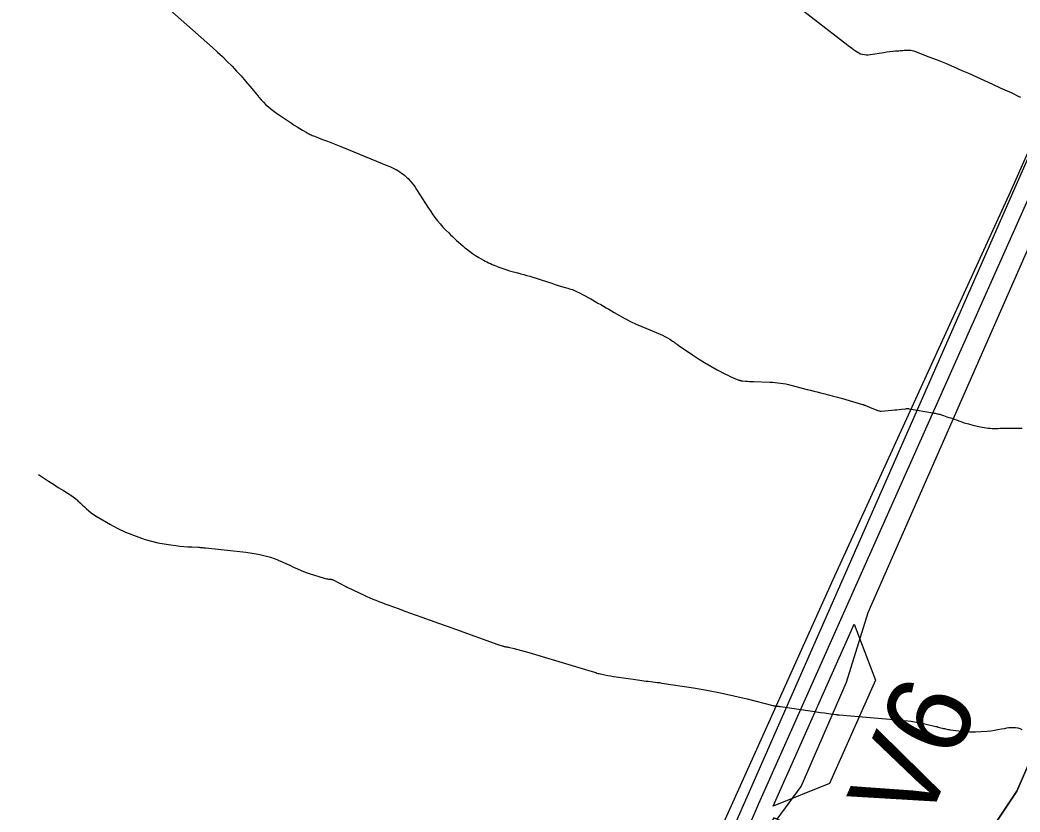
# Model space of a CAD drawing. Extents: x -629976 to -626966, y -1086511 to -1082952.
# Drawn here: x -628720.4 to -628543.5, y -1085440.3 to -1085300.1 of the extents above; entities that cross this region are included whole.
import ezdxf

# ---------------------------------------------------------------- set-up
doc = ezdxf.new("R2010")
doc.units = 0
for name, color, linetype in [('01_PARCELY_NÁVRH_PC', 7, 'Continuous'), ('01_VRSTEVNICE', 7, 'Continuous'), ('02_KULTURY STAV', 7, 'Continuous'), ('03_PC_NÁVRH', 7, 'Continuous'), ('03_PC_OBJEKTY_NÁVRH', 7, 'Continuous')]:
    doc.layers.add(name, color=color, linetype=linetype)

msp = doc.modelspace()

# ---------------------------------------------------------------- linework, layer by layer
at = {"layer": '01_PARCELY_NÁVRH_PC'}
for points in [[(-628504.59, -1085239), (-628671.58, -1085619.06)], [(-628665.65, -1085621.72), (-628622.61, -1085523.77), (-628623.14, -1085523.92), (-628620.48, -1085517.91), (-628606.61, -1085486.09), (-628587.08, -1085441.31), (-628586.49, -1085441.56), (-628582.26, -1085435.74), (-628574.23, -1085417.3), (-628570.41, -1085404.96), (-628501.92, -1085249.09)]]:
    msp.add_lwpolyline(points, dxfattribs=at)
at = {"layer": '01_VRSTEVNICE'}
for points in [[(-628697.46, -1085295.07), (-628686.37, -1085304.93), (-628685.49, -1085305.73), (-628684.62, -1085306.55), (-628683.77, -1085307.38), (-628682.94, -1085308.23), (-628682.12, -1085309.09), (-628681.32, -1085309.97), (-628680.55, -1085310.87), (-628679.78, -1085311.79), (-628678.57, -1085313.27), (-628678.18, -1085313.73), (-628677.78, -1085314.18), (-628677.36, -1085314.62), (-628676.94, -1085315.05), (-628676.49, -1085315.45), (-628676.03, -1085315.84), (-628675.55, -1085316.21), (-628675.06, -1085316.56), (-628672.41, -1085318.33), (-628671.93, -1085318.65), (-628671.44, -1085318.96), (-628670.95, -1085319.26), (-628670.46, -1085319.56), (-628669.82, -1085319.94), (-628669.64, -1085320.04), (-628669.47, -1085320.14), (-628669.29, -1085320.23), (-628669.11, -1085320.32), (-628668.92, -1085320.41), (-628668.74, -1085320.49), (-628668.55, -1085320.57), (-628668.37, -1085320.64), (-628666.96, -1085321.19), (-628666.07, -1085321.54), (-628665.19, -1085321.89), (-628664.3, -1085322.24), (-628663.41, -1085322.6), (-628655.39, -1085325.85), (-628655.02, -1085326), (-628654.66, -1085326.17), (-628654.3, -1085326.34), (-628653.95, -1085326.52), (-628653.92, -1085326.54), (-628653.59, -1085326.73), (-628653.26, -1085326.93), (-628652.95, -1085327.15), (-628652.64, -1085327.37), (-628652.34, -1085327.61), (-628652.06, -1085327.87), (-628651.79, -1085328.14), (-628651.52, -1085328.41), (-628651.41, -1085328.54), (-628651.11, -1085328.9), (-628650.82, -1085329.27), (-628650.55, -1085329.65), (-628650.29, -1085330.04), (-628648.72, -1085332.56), (-628648.32, -1085333.19), (-628647.91, -1085333.8), (-628647.49, -1085334.41), (-628647.05, -1085335.01), (-628646.6, -1085335.6), (-628646.13, -1085336.17), (-628645.63, -1085336.71), (-628645.11, -1085337.24), (-628644.61, -1085337.73), (-628644.26, -1085338.07), (-628643.91, -1085338.41), (-628643.56, -1085338.75), (-628643.21, -1085339.08), (-628642.85, -1085339.41), (-628642.48, -1085339.74), (-628642.12, -1085340.05), (-628641.74, -1085340.37), (-628641.46, -1085340.59), (-628640.94, -1085341), (-628640.4, -1085341.39), (-628639.84, -1085341.75), (-628639.27, -1085342.1), (-628638.46, -1085342.56), (-628638.15, -1085342.73), (-628637.85, -1085342.89), (-628637.54, -1085343.05), (-628637.22, -1085343.19), (-628636.91, -1085343.33), (-628636.59, -1085343.47), (-628636.27, -1085343.6), (-628635.95, -1085343.73), (-628635.9, -1085343.75), (-628635.56, -1085343.88), (-628635.21, -1085344.01), (-628634.86, -1085344.13), (-628634.51, -1085344.25), (-628634.31, -1085344.31), (-628633.85, -1085344.44), (-628633.39, -1085344.58), (-628632.93, -1085344.7), (-628632.47, -1085344.82), (-628632.35, -1085344.85), (-628631.83, -1085344.98), (-628631.31, -1085345.12), (-628630.79, -1085345.28), (-628630.28, -1085345.43), (-628626.94, -1085346.5), (-628626.36, -1085346.68), (-628625.79, -1085346.86), (-628625.22, -1085347.04), (-628624.65, -1085347.22), (-628624.02, -1085347.41), (-628623.76, -1085347.48), (-628623.5, -1085347.56), (-628623.24, -1085347.64), (-628622.98, -1085347.72), (-628622.73, -1085347.8), (-628622.47, -1085347.89), (-628622.23, -1085348), (-628621.98, -1085348.12), (-628621.45, -1085348.38), (-628620.95, -1085348.64), (-628620.45, -1085348.9), (-628619.95, -1085349.18), (-628619.46, -1085349.45), (-628619.16, -1085349.62), (-628618.68, -1085349.9), (-628618.2, -1085350.17), (-628617.72, -1085350.45), (-628617.24, -1085350.72), (-628616.76, -1085351), (-628616.28, -1085351.28), (-628615.81, -1085351.56), (-628615.33, -1085351.84), (-628614.38, -1085352.39), (-628613.42, -1085352.93), (-628612.44, -1085353.44), (-628611.45, -1085353.91), (-628610.44, -1085354.35), (-628607.21, -1085355.68), (-628606.77, -1085355.87), (-628606.34, -1085356.08), (-628605.92, -1085356.32), (-628605.5, -1085356.57), (-628604.99, -1085356.9), (-628604.84, -1085356.99), (-628604.7, -1085357.1), (-628604.56, -1085357.2), (-628604.42, -1085357.31), (-628604.28, -1085357.42), (-628604.14, -1085357.53), (-628604, -1085357.63), (-628603.85, -1085357.73), (-628601.49, -1085359.34), (-628600.42, -1085360.05), (-628599.33, -1085360.72), (-628598.22, -1085361.36), (-628597.09, -1085361.98), (-628595.63, -1085362.74), (-628595.22, -1085362.95), (-628594.81, -1085363.15), (-628594.39, -1085363.34), (-628593.96, -1085363.51), (-628593.26, -1085363.8), (-628593.18, -1085363.83), (-628593.1, -1085363.85), (-628593.02, -1085363.88), (-628592.94, -1085363.9), (-628592.86, -1085363.92), (-628592.77, -1085363.93), (-628592.69, -1085363.94), (-628592.6, -1085363.95), (-628592.08, -1085364), (-628591.74, -1085364.02), (-628591.39, -1085364.04), (-628591.04, -1085364.06), (-628590.7, -1085364.07), (-628587.8, -1085364.17), (-628587.33, -1085364.19), (-628586.85, -1085364.22), (-628586.38, -1085364.27), (-628585.91, -1085364.33), (-628585.44, -1085364.41), (-628584.97, -1085364.5), (-628584.51, -1085364.6), (-628584.05, -1085364.71), (-628581.19, -1085365.45), (-628580.59, -1085365.61), (-628580, -1085365.76), (-628579.41, -1085365.91), (-628578.82, -1085366.06), (-628578.54, -1085366.13), (-628578.09, -1085366.25), (-628577.64, -1085366.36), (-628577.19, -1085366.47), (-628576.74, -1085366.59), (-628576.29, -1085366.7), (-628575.84, -1085366.82), (-628575.39, -1085366.94), (-628574.95, -1085367.07), (-628571.38, -1085368.11), (-628571.33, -1085368.13), (-628571.27, -1085368.15), (-628571.22, -1085368.17), (-628571.17, -1085368.18), (-628571.12, -1085368.2), (-628571.07, -1085368.22), (-628571.02, -1085368.25), (-628570.97, -1085368.27), (-628569.73, -1085368.8), (-628569.58, -1085368.86), (-628569.44, -1085368.92), (-628569.3, -1085368.97), (-628569.15, -1085369.03), (-628569.13, -1085369.04), (-628569, -1085369.08), (-628568.86, -1085369.13), (-628568.73, -1085369.17), (-628568.6, -1085369.21), (-628568.4, -1085369.27), (-628568.36, -1085369.28), (-628568.33, -1085369.29), (-628568.29, -1085369.3), (-628568.25, -1085369.31), (-628568.21, -1085369.31), (-628568.17, -1085369.31), (-628568.13, -1085369.31), (-628568.09, -1085369.31), (-628566.19, -1085369.13), (-628565.76, -1085369.09), (-628565.33, -1085369.05), (-628564.9, -1085369), (-628564.47, -1085368.96), (-628563.74, -1085368.88), (-628563.67, -1085368.87), (-628563.6, -1085368.87), (-628563.54, -1085368.86), (-628563.47, -1085368.86), (-628563.39, -1085368.86), (-628563.36, -1085368.86), (-628563.33, -1085368.86), (-628563.3, -1085368.86), (-628563.27, -1085368.87), (-628563.24, -1085368.87), (-628563.21, -1085368.88), (-628563.18, -1085368.88), (-628563.15, -1085368.89), (-628558.98, -1085369.61), (-628558.77, -1085369.65), (-628558.57, -1085369.69), (-628558.36, -1085369.73), (-628558.15, -1085369.77), (-628557.94, -1085369.82), (-628557.74, -1085369.87), (-628557.54, -1085369.93), (-628557.33, -1085370), (-628557.09, -1085370.08), (-628556.77, -1085370.19), (-628556.45, -1085370.3), (-628556.12, -1085370.41), (-628555.8, -1085370.52), (-628554.16, -1085371.1), (-628553.4, -1085371.35), (-628552.64, -1085371.58), (-628551.87, -1085371.78), (-628551.1, -1085371.96), (-628550.22, -1085372.15), (-628549.88, -1085372.22), (-628549.53, -1085372.27), (-628549.19, -1085372.31), (-628548.84, -1085372.34), (-628548.8, -1085372.35), (-628548.47, -1085372.36), (-628548.13, -1085372.37), (-628547.8, -1085372.37), (-628547.46, -1085372.36), (-628547.13, -1085372.34), (-628546.79, -1085372.33), (-628546.46, -1085372.32), (-628546.12, -1085372.32), (-628544.98, -1085372.3), (-628544.08, -1085372.31), (-628543.17, -1085372.35)], [(-628583.63, -1085297.1), (-628574.74, -1085303.93), (-628574.3, -1085304.27), (-628573.85, -1085304.61), (-628573.41, -1085304.95), (-628572.97, -1085305.28), (-628572.63, -1085305.54), (-628572.34, -1085305.72), (-628572.05, -1085305.89), (-628571.73, -1085306.02), (-628571.41, -1085306.12), (-628571.07, -1085306.19), (-628570.74, -1085306.22), (-628570.4, -1085306.22), (-628570.06, -1085306.18), (-628567.61, -1085305.79), (-628567.09, -1085305.71), (-628566.58, -1085305.64), (-628566.06, -1085305.58), (-628565.54, -1085305.54), (-628565, -1085305.49), (-628564.75, -1085305.47), (-628564.5, -1085305.45), (-628564.25, -1085305.43), (-628564.01, -1085305.41), (-628563.96, -1085305.41), (-628563.73, -1085305.4), (-628563.51, -1085305.39), (-628563.28, -1085305.39), (-628563.05, -1085305.4), (-628562.83, -1085305.42), (-628562.61, -1085305.45), (-628562.39, -1085305.51), (-628562.18, -1085305.58), (-628559.66, -1085306.56), (-628558.19, -1085307.14), (-628556.73, -1085307.73), (-628555.27, -1085308.35), (-628553.82, -1085308.98), (-628552.64, -1085309.5), (-628551.23, -1085310.13), (-628549.83, -1085310.76), (-628548.42, -1085311.39), (-628547.02, -1085312.04), (-628545, -1085312.97), (-628544.62, -1085313.15), (-628544.23, -1085313.34), (-628543.85, -1085313.53), (-628543.47, -1085313.73)], [(-628717.17, -1085380.55), (-628716.3, -1085381.13), (-628715.43, -1085381.7), (-628714.55, -1085382.26), (-628713.67, -1085382.81), (-628712.77, -1085383.35), (-628711.9, -1085383.87), (-628711.45, -1085384.16), (-628711.02, -1085384.46), (-628710.6, -1085384.8), (-628710.2, -1085385.15), (-628710.2, -1085385.16), (-628709.81, -1085385.52), (-628709.43, -1085385.89), (-628709.05, -1085386.26), (-628708.67, -1085386.63), (-628708.28, -1085386.98), (-628707.88, -1085387.32), (-628707.45, -1085387.62), (-628707, -1085387.9), (-628704.46, -1085389.37), (-628703.13, -1085390.08), (-628701.78, -1085390.73), (-628700.39, -1085391.29), (-628698.98, -1085391.8), (-628698.33, -1085392.01), (-628697.21, -1085392.33), (-628696.08, -1085392.61), (-628694.94, -1085392.83), (-628693.78, -1085393), (-628692.88, -1085393.11), (-628692.17, -1085393.19), (-628691.45, -1085393.25), (-628690.74, -1085393.31), (-628690.02, -1085393.35), (-628688.93, -1085393.41), (-628688.76, -1085393.42), (-628688.59, -1085393.43), (-628688.42, -1085393.44), (-628688.25, -1085393.45), (-628688.08, -1085393.47), (-628687.92, -1085393.48), (-628687.75, -1085393.5), (-628687.58, -1085393.52), (-628682.68, -1085394.02), (-628681.58, -1085394.15), (-628680.49, -1085394.29), (-628679.4, -1085394.47), (-628678.31, -1085394.66), (-628677.54, -1085394.81), (-628676.85, -1085394.96), (-628676.16, -1085395.15), (-628675.5, -1085395.38), (-628674.84, -1085395.64), (-628674.77, -1085395.67), (-628674.09, -1085395.97), (-628673.41, -1085396.28), (-628672.73, -1085396.59), (-628672.06, -1085396.92), (-628672.05, -1085396.92), (-628671.37, -1085397.24), (-628670.68, -1085397.53), (-628669.98, -1085397.79), (-628669.27, -1085398.04), (-628666.61, -1085398.89), (-628666.43, -1085398.94), (-628666.24, -1085398.98), (-628666.04, -1085399.01), (-628665.85, -1085399.04), (-628665.6, -1085399.06), (-628665.53, -1085399.06), (-628665.46, -1085399.07), (-628665.39, -1085399.08), (-628665.33, -1085399.09), (-628665.26, -1085399.11), (-628665.19, -1085399.13), (-628665.13, -1085399.15), (-628665.07, -1085399.18), (-628662.8, -1085400.37), (-628662.78, -1085400.38), (-628662.76, -1085400.39), (-628662.74, -1085400.4), (-628662.72, -1085400.41), (-628662.7, -1085400.42), (-628662.68, -1085400.43), (-628662.65, -1085400.44), (-628662.63, -1085400.46), (-628662.61, -1085400.47), (-628662.58, -1085400.48), (-628662.54, -1085400.5), (-628662.51, -1085400.52), (-628662.47, -1085400.53), (-628659.58, -1085401.89), (-628659.06, -1085402.13), (-628658.54, -1085402.36), (-628658.02, -1085402.58), (-628657.49, -1085402.8), (-628656.96, -1085403.01), (-628656.43, -1085403.21), (-628655.9, -1085403.41), (-628655.37, -1085403.61), (-628654.4, -1085403.96), (-628653.39, -1085404.33), (-628652.37, -1085404.7), (-628651.36, -1085405.06), (-628650.34, -1085405.43), (-628649.38, -1085405.77), (-628647.89, -1085406.31), (-628646.4, -1085406.85), (-628644.9, -1085407.38), (-628643.41, -1085407.92), (-628635.92, -1085410.63), (-628635.74, -1085410.69), (-628635.55, -1085410.75), (-628635.35, -1085410.81), (-628635.16, -1085410.87), (-628635.02, -1085410.91), (-628634.9, -1085410.94), (-628634.78, -1085410.97), (-628634.66, -1085410.99), (-628634.53, -1085411.02), (-628634.41, -1085411.04), (-628634.29, -1085411.06), (-628634.17, -1085411.09), (-628634.05, -1085411.12), (-628633, -1085411.36), (-628632.35, -1085411.51), (-628631.71, -1085411.67), (-628631.07, -1085411.85), (-628630.44, -1085412.03), (-628619.22, -1085415.42), (-628619.01, -1085415.49), (-628618.81, -1085415.55), (-628618.6, -1085415.61), (-628618.39, -1085415.67), (-628618.17, -1085415.73), (-628617.96, -1085415.78), (-628617.75, -1085415.83), (-628617.54, -1085415.88), (-628616.97, -1085415.99), (-628616.46, -1085416.09), (-628615.96, -1085416.18), (-628615.46, -1085416.26), (-628614.96, -1085416.34), (-628611.58, -1085416.83), (-628611.2, -1085416.89), (-628610.82, -1085416.94), (-628610.44, -1085416.99), (-628610.06, -1085417.04), (-628609.67, -1085417.09), (-628609.29, -1085417.14), (-628608.91, -1085417.18), (-628608.52, -1085417.23), (-628608.5, -1085417.23), (-628608.1, -1085417.28), (-628607.71, -1085417.33), (-628607.31, -1085417.38), (-628606.92, -1085417.44), (-628601.31, -1085418.31), (-628598.92, -1085418.71), (-628596.53, -1085419.17), (-628594.16, -1085419.69), (-628591.8, -1085420.26), (-628587.29, -1085421.42), (-628587.19, -1085421.44), (-628587.09, -1085421.46), (-628586.99, -1085421.48), (-628586.89, -1085421.5), (-628586.81, -1085421.51), (-628586.75, -1085421.52), (-628586.69, -1085421.53), (-628586.64, -1085421.53), (-628586.58, -1085421.54), (-628586.52, -1085421.54), (-628586.46, -1085421.55), (-628586.41, -1085421.55), (-628586.35, -1085421.56), (-628586.29, -1085421.56), (-628586.2, -1085421.57), (-628586.11, -1085421.58), (-628586.02, -1085421.59), (-628585.93, -1085421.6), (-628580.22, -1085422.44), (-628579.51, -1085422.54), (-628578.81, -1085422.65), (-628578.1, -1085422.74), (-628577.39, -1085422.84), (-628576.12, -1085423.02), (-628576.05, -1085423.03), (-628575.98, -1085423.04), (-628575.9, -1085423.04), (-628575.83, -1085423.05), (-628575.76, -1085423.06), (-628575.69, -1085423.06), (-628575.62, -1085423.07), (-628575.54, -1085423.07), (-628565.23, -1085423.94), (-628564.01, -1085424.06), (-628562.8, -1085424.22), (-628561.59, -1085424.44), (-628560.39, -1085424.68), (-628558.44, -1085425.12), (-628558.21, -1085425.17), (-628557.99, -1085425.23), (-628557.77, -1085425.29), (-628557.55, -1085425.35), (-628557.52, -1085425.36), (-628557.31, -1085425.41), (-628557.11, -1085425.47), (-628556.9, -1085425.52), (-628556.69, -1085425.57), (-628556.49, -1085425.61), (-628556.28, -1085425.66), (-628556.07, -1085425.69), (-628555.86, -1085425.72), (-628554.34, -1085425.92), (-628553.38, -1085426.01), (-628552.41, -1085426.07), (-628551.43, -1085426.06), (-628550.46, -1085426.02), (-628549.37, -1085425.95), (-628548.72, -1085425.89), (-628548.07, -1085425.81), (-628547.43, -1085425.7), (-628546.78, -1085425.58), (-628546.28, -1085425.47), (-628545.89, -1085425.4), (-628545.5, -1085425.34), (-628545.1, -1085425.3), (-628544.71, -1085425.29), (-628544.32, -1085425.31), (-628543.94, -1085425.37), (-628543.58, -1085425.5), (-628543.23, -1085425.67)]]:
    msp.add_lwpolyline(points, dxfattribs=at)
at = {"layer": '02_KULTURY STAV'}
for points in [[(-628469.63, -1085290.92), (-628465.72, -1085301), (-628476.54, -1085321.48), (-628487.98, -1085343.92), (-628499.57, -1085372), (-628506.26, -1085388.1), (-628515.74, -1085412.3), (-628525.97, -1085436.31), (-628526.52, -1085437.68), (-628535.02, -1085458.9), (-628536, -1085461.41), (-628536.27, -1085468.02), (-628537.33, -1085471.15), (-628542.26, -1085469.22), (-628539.36, -1085462.61), (-628548.94, -1085458.33), (-628555.75, -1085455.27), (-628551.35, -1085447.51), (-628544.07, -1085436.61), (-628519.32, -1085379.74), (-628506.1, -1085348.33), (-628494.74, -1085322.98), (-628488.5, -1085307.32), (-628479.37, -1085287.45)], [(-628519.32, -1085379.74), (-628544.07, -1085436.61), (-628551.35, -1085447.51), (-628555.75, -1085455.27), (-628565.12, -1085451.07), (-628580.75, -1085444.02), (-628587.08, -1085441.31), (-628606.61, -1085486.09), (-628620.48, -1085517.91), (-628623.14, -1085523.92), (-628603.34, -1085518.29), (-628577.42, -1085515.26), (-628553.59, -1085525.92), (-628540.85, -1085532)]]:
    msp.add_lwpolyline(points, dxfattribs=at)
at = {"layer": '03_PC_NÁVRH'}
msp.add_lwpolyline([(-629148.04, -1085548.66), (-628975.58, -1085561.05), (-628965.11, -1085562.93), (-628930.36, -1085576.19), (-628913.61, -1085582.35), (-628886.37, -1085587.46), (-628866.01, -1085593.03), (-628842.08, -1085600.86), (-628816.54, -1085615.19), (-628803.43, -1085624.52), (-628784.1, -1085634.19), (-628761.29, -1085644.58), (-628740.33, -1085654.09), (-628727.7, -1085658.08), (-628715.96, -1085658.66), (-628703.79, -1085657.45), (-628694.51, -1085652.8), (-628684.23, -1085645.88), (-628675.78, -1085635.09), (-628626.01, -1085523.21), (-628589.74, -1085438.8), (-628499.95, -1085237.06)], dxfattribs=at)
at = {"layer": '03_PC_OBJEKTY_NÁVRH'}
msp.add_lwpolyline([(-628714.09, -1085655.43), (-628702.73, -1085653.01), (-628690.99, -1085646.57), (-628684.06, -1085640.41), (-628678.01, -1085632.64), (-628672.97, -1085620.74), (-628637, -1085539.22), (-628595.63, -1085441.5), (-628576.59, -1085399.12), (-628545.15, -1085330.36), (-628503.3, -1085235.81)], dxfattribs=at)
msp.add_lwpolyline([(-628572.86, -1085407.05), (-628569.07, -1085416.95), (-628577.21, -1085435.22), (-628587.22, -1085439.25)], close=True, dxfattribs=at)

# ---------------------------------------------------------------- texts
msp.add_text('V6', height=15, rotation=66.0072, dxfattribs=at).set_placement((-628560.62, -1085443.66))

doc.saveas('drawing.dxf')
